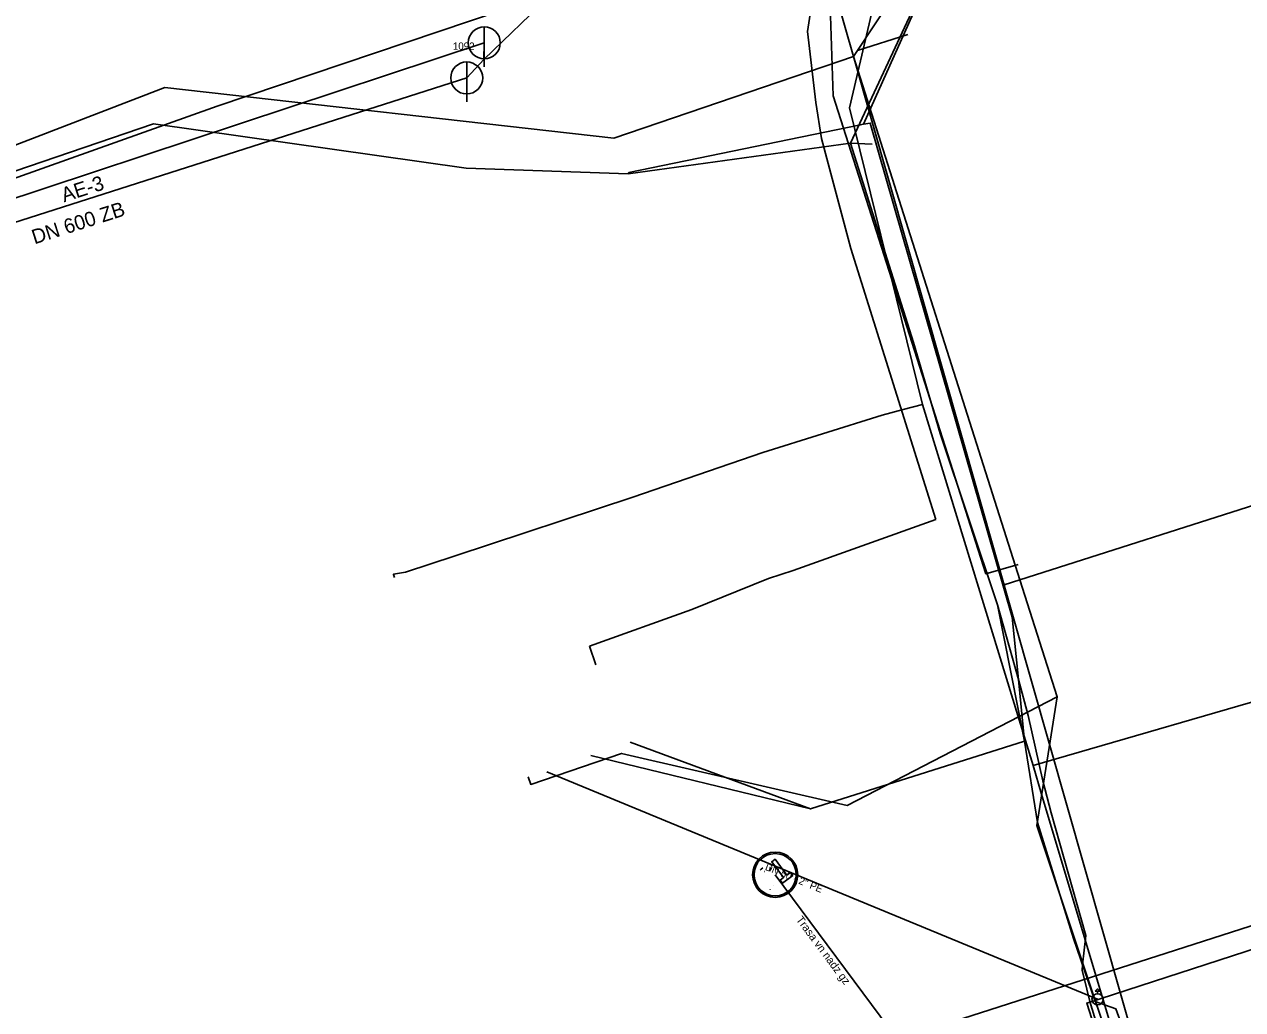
# Model space of a CAD drawing. Extents: x -493753 to -49291, y -1127285 to -112662.
# Drawn here: x -493443.1 to -493367, y -1126808.1 to -1126746.6 of the extents above; entities that cross this region are included whole.
import ezdxf

# ---------------------------------------------------------------- set-up
doc = ezdxf.new("R2010")
doc.units = 0
for name, color, linetype in [('Vrstva 1', 7, 'Continuous'), ('Vrstva 11', 7, 'Continuous'), ('Vrstva 15', 7, 'Continuous'), ('Vrstva 17', 7, 'Continuous'), ('Vrstva 19', 7, 'Continuous'), ('Vrstva 20', 7, 'Continuous'), ('Vrstva 22', 7, 'Continuous'), ('Vrstva 24', 7, 'Continuous'), ('Vrstva 35', 7, 'Continuous'), ('Vrstva 39', 7, 'Continuous'), ('Vrstva 5', 7, 'Continuous'), ('Vrstva 6', 7, 'Continuous'), ('Vrstva 8', 7, 'Continuous'), ('Vrstva 9', 7, 'Continuous')]:
    doc.layers.add(name, color=color, linetype=linetype)

# ---------------------------------------------------------------- blocks, each defined once
blk = doc.blocks.new('_SACHT')
at = {"layer": 'Vrstva 1'}
blk.add_line((0, 0.035), (0, 0.05), dxfattribs=at)
blk.add_lwpolyline([(-0.015, 0.05), (0, 0.065), (0.015, 0.05), (0.0025, 0.05)], close=True, dxfattribs=at)
blk.add_circle((0, 0), 0.035, dxfattribs=at)
blk = doc.blocks.new('_SACH0')
at = {"layer": 'Vrstva 1'}
blk.add_line((0, 0.05), (0, -0.075), dxfattribs=at)
blk.add_circle((0, 0), 0.05, dxfattribs=at)

msp = doc.modelspace()

# ---------------------------------------------------------------- linework, layer by layer
at = {"layer": 'Vrstva 1'}
for points in [[(-493386.97, -1126735.58), (-493387.91, -1126736.18), (-493388.12, -1126737.11), (-493391.54, -1126751.8), (-493386.98, -1126770.32), (-493380.08, -1126792.87), (-493379.55, -1126794.65), (-493376.82, -1126803.75), (-493374.41, -1126811.8), (-493372.08, -1126819.97)], [(-493386.98, -1126770.32), (-493388.2, -1126770.64), (-493389.51, -1126770.99), (-493396.96, -1126773.32), (-493405.09, -1126776.1), (-493416.17, -1126779.76), (-493419.28, -1126780.78), (-493420.03, -1126780.91), (-493420.03, -1126780.94), (-493419.97, -1126781.13)], [(-493360.73, -1126784.87), (-493360.07, -1126787.07), (-493362.98, -1126787.91), (-493380.08, -1126792.87)]]:
    msp.add_lwpolyline(points, dxfattribs=at)
at = {"layer": 'Vrstva 11'}
for points in [[(-493384.4, -1126738.16), (-493389.01, -1126739.69), (-493392.38, -1126744.8), (-493391.29, -1126748.6)], [(-493384.4, -1126738.16), (-493391.04, -1126748.21)], [(-493391.04, -1126748.21), (-493387.9, -1126747.22)], [(-493391.04, -1126748.21), (-493391.29, -1126748.6)], [(-493391.29, -1126748.6), (-493406.26, -1126753.68), (-493434.32, -1126750.53), (-493463.4, -1126761.72), (-493469.71, -1126766.76), (-493508.82, -1126780.08), (-493512.23, -1126781.43), (-493514.74, -1126783.85), (-493516.23, -1126787.62), (-493513.31, -1126795.21), (-493526.86, -1126800.13), (-493533.75, -1126808.59)], [(-493354.32, -1126869.92), (-493371.26, -1126818.85), (-493391.29, -1126748.6)], [(-493391.29, -1126748.6), (-493380.9, -1126781.26)], [(-493381.89, -1126781.58), (-493363.75, -1126775.8), (-493357.69, -1126776.22)], [(-493380.9, -1126781.26), (-493378.57, -1126788.57)], [(-493378.57, -1126788.57), (-493391.69, -1126795.35), (-493405.78, -1126792.11), (-493411.46, -1126794.04), (-493411.62, -1126793.57)], [(-493378.57, -1126788.57), (-493379.85, -1126796.61), (-493372.3, -1126819.19), (-493362.25, -1126815.91)]]:
    msp.add_lwpolyline(points, dxfattribs=at)
at = {"layer": 'Vrstva 15'}
for p, q in [((-493414.39, -1126748.78), (-493406.54, -1126741.21)), ((-493495.17, -1126774.45), (-493414.36, -1126747.74)), ((-493414.36, -1126747.74), (-493414.39, -1126748.78)), ((-493415.46, -1126749.93), (-493414.39, -1126748.78)), ((-493462.33, -1126764.92), (-493415.46, -1126749.93))]:
    msp.add_line(p, q, dxfattribs=at)
at = {"layer": 'Vrstva 20'}
for points in [[(-493174.93, -1126671.26), (-493174.82, -1126671.68), (-493179.54, -1126673.79), (-493215.57, -1126683.72), (-493222.63, -1126681.54), (-493265.09, -1126696.88), (-493320.52, -1126714.46), (-493431.04, -1126751.7), (-493465.39, -1126763.9), (-493480.64, -1126768.71), (-493511.98, -1126779.09), (-493513.24, -1126779.47)], [(-493298.03, -1126782.15), (-493376.73, -1126807.69), (-493366.42, -1126840.02), (-493348.23, -1126899.22), (-493335.1, -1126898.15)], [(-493376.05, -1126807.46), (-493410.45, -1126793.26), (-493410.45, -1126793.26)]]:
    msp.add_lwpolyline(points, dxfattribs=at)
at = {"layer": 'Vrstva 35'}
for p, q in [((-493393.28, -1126741.03), (-493394.17, -1126747.04)), ((-493394.17, -1126747.04), (-493393.65, -1126751.47)), ((-493393.65, -1126751.47), (-493393.3, -1126753.72)), ((-493393.3, -1126753.72), (-493391.47, -1126760.57)), ((-493391.47, -1126760.57), (-493386.15, -1126777.49)), ((-493386.15, -1126777.49), (-493395.06, -1126780.68)), ((-493396.6, -1126781.18), (-493401.39, -1126783.11)), ((-493395.06, -1126780.68), (-493396.6, -1126781.18)), ((-493401.39, -1126783.11), (-493407.78, -1126785.41)), ((-493407.78, -1126785.41), (-493407.4, -1126786.58))]:
    msp.add_line(p, q, dxfattribs=at)
at = {"layer": 'Vrstva 39'}
for points in [[(-493391.48, -1126754), (-493384.29, -1126738.55), (-493336.24, -1126722.43), (-493208.49, -1126679.18), (-493188.86, -1126672.37)], [(-493390.68, -1126752.82), (-493384.29, -1126738.55)], [(-493534.53, -1126806.94), (-493532.56, -1126804.44), (-493531.29, -1126801.12), (-493516.96, -1126796.08), (-493513.58, -1126794.87), (-493515.88, -1126787.64), (-493514.95, -1126784.12), (-493510.44, -1126780.73), (-493472.56, -1126767.69), (-493465.56, -1126763.09), (-493458.46, -1126760.65), (-493452.37, -1126758.7), (-493435.03, -1126752.8), (-493415.49, -1126755.56), (-493405.37, -1126755.91)], [(-493390.68, -1126752.82), (-493390.97, -1126752.88), (-493405.33, -1126755.84), (-493405.37, -1126755.91)], [(-493390.68, -1126752.82), (-493390.25, -1126752.75), (-493381.39, -1126783.59), (-493381, -1126787.49)], [(-493405.37, -1126755.91), (-493391.48, -1126754)], [(-493391.48, -1126754), (-493387.55, -1126766.45), (-493385.88, -1126772.13), (-493382.3, -1126782.83)], [(-493390.13, -1126754.07), (-493391.48, -1126754)], [(-493382.3, -1126782.83), (-493381, -1126787.49)], [(-493382.3, -1126782.83), (-493380.62, -1126791.35)], [(-493381, -1126787.49), (-493380.62, -1126791.35)], [(-493376.1, -1126809.04), (-493376.53, -1126807.6), (-493376.72, -1126806.82), (-493377.02, -1126805.63), (-493376.99, -1126805.31), (-493376.79, -1126803.48), (-493378.95, -1126795.81), (-493379.47, -1126793.81), (-493380.38, -1126789.73), (-493381, -1126787.49)], [(-493393.99, -1126795.57), (-493405.25, -1126791.4)], [(-493380.62, -1126791.35), (-493383.12, -1126792.14), (-493393.99, -1126795.57)], [(-493380.62, -1126791.35), (-493379.81, -1126796.41), (-493377.55, -1126803.67), (-493376.2, -1126807.6), (-493374.91, -1126808.06), (-493372, -1126816.01), (-493373.15, -1126816.68), (-493372.15, -1126819.47), (-493367.06, -1126818.18)], [(-493393.99, -1126795.57), (-493407.71, -1126792.24)]]:
    msp.add_lwpolyline(points, dxfattribs=at)
at = {"layer": 'Vrstva 5'}
msp.add_lwpolyline([(-493315.34, -1126725.38), (-493316.79, -1126725.53), (-493320.12, -1126725.86), (-493326.66, -1126725.85), (-493332.14, -1126724.13), (-493336.38, -1126721.99), (-493360.9, -1126729.58), (-493384.77, -1126737.05), (-493389.29, -1126738.7), (-493390.46, -1126740.52), (-493392.78, -1126744.79), (-493392.57, -1126751.04), (-493383.04, -1126780.89), (-493381.02, -1126780.32)], dxfattribs=at)
at = {"layer": 'Vrstva 6'}
for points in [[(-493324.2, -1126789.3), (-493388.54, -1126809.96)], [(-493388.54, -1126809.96), (-493396.19, -1126799.68)]]:
    msp.add_lwpolyline(points, dxfattribs=at)
at = {"layer": 'Vrstva 8'}
msp.add_lwpolyline([(-493395.091, -1126799.73), (-493395.739, -1126800.216), (-493395.885, -1126800.022), (-493395.669, -1126799.86), (-493396.409, -1126798.875), (-493396.197, -1126798.715), (-493395.457, -1126799.701), (-493395.237, -1126799.536)], close=True, dxfattribs=at)
for points in [[(-493396.967, -1126799.249), (-493397.074, -1126799.336), (-493397.123, -1126799.397)], [(-493396.874, -1126799.485), (-493396.865, -1126799.478)], [(-493396.53, -1126799.466), (-493396.509, -1126799.236), (-493396.518, -1126799.225)], [(-493396.51, -1126800.608), (-493396.505, -1126800.614)], [(-493396.286, -1126800.358), (-493396.288, -1126800.36)]]:
    msp.add_lwpolyline(points, dxfattribs=at)
for radius in [1.412, 1.32]:
    msp.add_circle((-493396.19, -1126799.68), radius, dxfattribs=at)

# ---------------------------------------------------------------- block references
at = {"layer": 'Vrstva 17', "xscale": 19.997500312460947, "yscale": 19.997500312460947}
for p in [(-493414.36, -1126747.74), (-493415.46, -1126749.93)]:
    msp.add_blockref('_SACH0', p, dxfattribs=at)
at = {"layer": 'Vrstva 22', "xscale": 9.998750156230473, "yscale": 9.998750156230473}
msp.add_blockref('_SACHT', (-493376.05, -1126807.46), dxfattribs=at)

# ---------------------------------------------------------------- texts
at = {"layer": 'Vrstva 19'}
msp.add_text('1092', height=0.4549, dxfattribs=at).set_placement((-493416.323, -1126748.17))
for s, p in [('AE-3', (-493440.61, -1126757.696)), ('DN 600 ZB', (-493442.457, -1126760.325))]:
    msp.add_text(s, height=0.9099, rotation=17.73536, dxfattribs=at).set_placement(p)
at = {"layer": 'Vrstva 24'}
msp.add_text("DN 50 - 2'' PE", height=0.455, rotation=337.56983, dxfattribs=at).set_placement((-493396.86, -1126799.365))
at = {"layer": 'Vrstva 9'}
msp.add_text('Trasa vn nadz gz', height=0.5, rotation=306.66983, dxfattribs=at).set_placement((-493394.912, -1126802.491))

doc.saveas('drawing.dxf')
